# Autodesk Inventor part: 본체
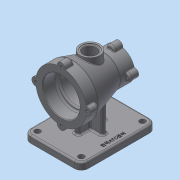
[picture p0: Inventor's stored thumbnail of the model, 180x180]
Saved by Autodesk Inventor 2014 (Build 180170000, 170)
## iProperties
Created: 2020-12
Part Number: 본체
Material: 일반
Document SubType Name: Modeling
Designer: net
Density: 1 g/cm^3
Appearance: 기본값
Mass: 381.333 g
Surface Area: 852.02 cm^2
Volume: 381.333 cm^3
Author: net
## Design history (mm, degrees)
sketch "스케치1"
  geometry: L1 (-50, -65)-(50, -65); L2 (50, -65)-(50, 65); L3 (50, 65)-(-50, 65); L4 (-50, 65)-(-50, -65); L5 (-50, -65)-(50, 65); L6 (50, -65)-(-50, 65); L7 (4, 24)-(-4, 24); L8 (-4, 24)-(-4, 4); L9 (-4, 4)-(-25, 4); L10 (-25, 4)-(-25, -4); L11 (-25, -4)-(-4, -4); L12 (-4, -4)-(-4, -24); L13 (-4, -24)-(4, -24); L14 (4, -24)-(4, -4); L15 (4, -4)-(25, -4); L16 (25, -4)-(25, 4); L17 (25, 4)-(4, 4); L18 (4, 4)-(4, 24); 5 further points
  constraints: 36 end point, 6 midpoint, 6 parallel, 5 perpendicular, 4 horizontal, 3 equal length, 3 horizontal alignment, 3 vertical alignment, 1 vertical
  dimensions: "d1" = 130 distance of L1.end L2.end; "d2" = 100 distance of L2.end L3.end; "d3" = 8 distance of L15.end L16.end; "d4" = 48 distance between parallel lines of L13 L7; "d5" = 50 distance between parallel lines of L16 L10
extrude "돌출1" new body sketch "스케치1" distance "d6" = 12; taper "d7" = 0 deg
extrude "돌출2" join sketch "스케치1" distance "d8" = 82; taper "d9" = 0 deg
sketch "스케치2"
  geometry: L1 (24, 82)-(4, 82) reference; L2 (-4, 82)-(-24, 82) reference; L3 (4, 82)-(-4, 82) reference; L4 (-50, 82)-(50, 82); L5 (-50, 82)-(-50, 126); L6 (-50, 126)-(-30, 126); L7 (-30, 126)-(25, 109.5); L8 (25, 109.5)-(50, 109.5); L9 (50, 109.5)-(50, 82); L10 (-50, 114)-(-27, 114); L11 (-27, 114)-(-27, 108); L12 (-27, 108)-(20, 108); L13 (20, 108)-(20, 102); L14 (20, 102)-(50, 102); 2 further points
  constraints: 22 end point, 5 perpendicular, 4 parallel, 2 midpoint, 2 point on line, 1 horizontal
  dimensions: "d10" = 100 distance of L4.start L4.end; "d11" = 20 distance of L5.end L6.end; "d12" = 88 diameter of L6 L4; "d13" = 55 diameter of L8 L4; "d14" = 40 diameter of L14 L4; "d15" = 52 diameter of L12 L4; "d16" = 64 diameter of L10 L4; "d17" = 23 distance of L10.start L10.end; "d18" = 47 distance of L11.end L12.end; "d95" = 25 distance from line of L7.end L9
revolve "회전1" stored, may be unused: angle "d19" = 90 deg
revolve "회전2" stored, may be unused: angle "d20" = 90 deg
sketch "스케치3"
  geometry: C1 r 32 at (0, 0) reference; C2 r 7 at (0, 44); 2 further points
  constraints: 2 vertical alignment, 1 centre point, 1 other
  dimensions: "d21" = 14 diameter of C2
extrude "돌출3" join sketch "스케치3" distance "d22" = 15; taper "d23" = 0 deg
sketch "스케치4"
  geometry: A1 r 7 centre (0, 0) between (6.978, -0.557) and (-6.978, -0.557) reference; 1 further point
hole "구멍1" sketch "스케치4" at (0, 0) diameter "d24" = 4.134; stored, may be unused: countersink angle "d28" = 90 deg, drill point angle "d30" = 118 deg; dims "d25" = 9, "d26" = 4, "d27" = 2, "d29" = 11
sketch "스케치5"
  geometry: C1 r 20 at (0, 0) reference; C2 r 7 at (0, -27.5); 2 further points
  constraints: 2 vertical alignment, 1 centre point, 1 other
  dimensions: "d34" = 14 diameter of C2
extrude "돌출4" join sketch "스케치5" distance "d35" = 15; taper "d36" = 0 deg
sketch "스케치6"
  geometry: A1 r 7 centre (0, 0) between (-6.943, 0.891) and (6.943, 0.891) reference; 1 further point
hole "구멍2" sketch "스케치6" at (0, 0) diameter "d37" = 4.134; stored, may be unused: countersink angle "d41" = 90 deg, drill point angle "d43" = 118 deg; dims "d38" = 9, "d39" = 4, "d40" = 2, "d42" = 11
sketch "스케치7"
  geometry: L1 (-30, 126)-(25, 109.5) reference; L2 (-50, 125.443)-(-50, 133) reference; L3 (0, 111)-(0, 127); L4 (0, 127)-(-17, 127); L5 (-17, 127)-(-17, 111); L6 (-17, 111)-(0, 111); L7 (50, 102)-(50, 62) reference; 3 further points
  constraints: 8 end point, 3 perpendicular, 1 midpoint, 1 parallel
  dimensions: "d51" = 50 distance between parallel lines of L2 L3; "d52" = 34 diameter of L5 L3; "d53" = 16 distance of L4.end L5.end; "d54" = 45 distance from line of L4 point (50, 82)
revolve "회전3" sketch "스케치7" stored, may be unused: angle "d55" = 90 deg
fillet "모깎기2" dims "d56" = 1
hole "구멍3" diameter "d59" = 22; stored, may be unused: countersink angle "d63" = 90 deg, drill point angle "d65" = 118 deg; dims "d57" = 10, "d58" = 10, "d60" = 9, "d61" = 28, "d62" = 1, "d64" = 30
chamfer "모따기1" distance "d66" = 1; stored, may be unused: second distance "d67" = 2, angle "d68" = 45 deg
fillet "모깎기3" dims "d69" = 3
fillet "모깎기4" dims "d70" = 3
fillet "모깎기5" dims "d71" = 3
chamfer "모따기2" distance "d72" = 1; stored, may be unused: second distance "d73" = 2, angle "d74" = 45 deg
fillet "모깎기6" dims "d75" = 12
sketch "스케치8"
  geometry: A1 r 12 centre (-38, 53) between (-38, 65) and (-50, 53) reference; A2 r 12 centre (-38, -53) between (-50, -53) and (-38, -65) reference; A3 r 12 centre (38, -53) between (38, -65) and (50, -53) reference; A4 r 12 centre (38, 53) between (50, 53) and (38, 65) reference; 1 further point
hole "구멍4" sketch "스케치8" at (38, -53), (38, 53), (-38, 53), (-38, -53) diameter "d76" = 10; stored, may be unused: countersink angle "d80" = 90 deg, drill point angle "d82" = 118 deg; dims "d77" = 9, "d78" = 28, "d79" = 1, "d81" = 30
fillet "모깎기7" dims "d83" = 3
fillet "모깎기8" dims "d84" = 3
fillet "모깎기9" dims "d88" = 1
sketch "스케치9"
  geometry: L1 (50, -53)-(50, 53) reference; 2 further points
  constraints: 1 horizontal alignment, 1 other
  dimensions: "d92" = 10 distance from line of L1 point (40, 0)
extrude "돌출5" join sketch "스케치9" distance "d93" = 0.5; taper "d94" = 0 deg
node "솔리드1"
pattern_circular "원형 패턴1" dims angle "d32" = 360 deg
pattern_circular "원형 패턴2" dims angle "d45" = 360 deg
pattern_circular "원형 패턴4" dims angle "d86" = 360 deg
pattern_circular "원형 패턴5" dims angle "d90" = 360 deg
